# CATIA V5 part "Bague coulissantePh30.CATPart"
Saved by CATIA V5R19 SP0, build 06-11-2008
Part number: Bague coulissante
Bounding box of the stored display mesh (mm): x -20 to 20, y -20 to 20, z 1.42 to 25
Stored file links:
  C:\Users\Laurent\Desktop\Sujet National E33\CFAO Catia\Bague coulissantePh30.CATPart
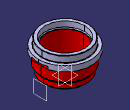
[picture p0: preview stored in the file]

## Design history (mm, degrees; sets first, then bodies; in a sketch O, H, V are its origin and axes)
Body1 (main body)
  Sketch1 on xy-plane, origin (0, 0, 0), H (1, 0, 0), V (0, 1, 0)
    circle A1 centre (0, 0) radius 22.5
    radius A1 = 22.5
  Pad1: profile Sketch1, direction (0, 0, 1), length 25
  Sketch2 on end face of Pad1, origin (0, 0, 25), H (1, 0, 0), V (0, 1, 0)
    circle A1 centre (0, 0) radius 17.45
    radius A1 = 17.45
  Pocket1: profile Sketch2, direction (0, 0, -1), length 4.78, outer side
  Sketch3 on end face of Pad1, origin (0, 0, 25), H (1, 0, 0), V (0, 1, 0)
    circle A1 centre (0, 0) radius 20
    radius A1 = 20
  Pocket2: profile Sketch3, direction (0, 0, -1), length 10, outer side
  Sketch4 on end face of Pad1, origin (0, 0, 25), H (1, 0, 0), V (0, 1, 0)
    circle A1 centre (0, 0) radius 10
    radius A1 = 10
  Pocket3: profile Sketch4, direction (0, 0, -1), through (limit type 3)
  Sketch5 on end face of Pad1, origin (0, 0, 25), H (1, 0, 0), V (0, 1, 0)
    circle A1 centre (0, 0) radius 14.95
    radius A1 = 14.95
  Pocket4: profile Sketch5, direction (0, 0, -1), length 4.78
  Sketch6 on zx-plane, origin (0, 0, 0), H (-1, 0, 0), V (0, 0, 1)
    axis line L1 (-25.6583, 20.6) -> (32.7674, 20.6)
    arc A1 centre (14.79, 20.6) radius 0.5 from (14.79, 20.1) to (14.79, 21.1) ccw
    point P3 (14.79, 20.6)
    reference projected line E1 (-17.45, 25) -> (17.45, 25) from edge [face of Pocket1 from Sketch2.A1 | end face of Pad1]
    line L2 (14.79, 20.1) -> (0, 20.1)
    point P4 (0, 20.1)
    line L3 (14.79, 21.1) -> (0, 21.1)
    point P5 (0, 21.1)
    line L4 (0, 20.1) -> (0, 21.1)
    reference projected line E2 through (0, 0) direction (0, 1) from axis of face of Pocket1 from Sketch2.A1
    distance L1 E1 = 4.4
    radius A1 = 0.5
    distance A1 E2 = 15.29
    horizontal: L1 H, L2 H, L3 H
    coincidence: P3 L1, P4 V, P5 V
    tangency: L3 A1, L2 A1
    vertical: L4 V
  Groove1: profile Sketch6, axis axis of face of Pocket2 from Sketch3.A1, angle 360
  Fillet1: radius 0.3, on edge [face of Pocket1 from Sketch2.A1 | end face of Pad1]; edge [end face of Pocket1 | face of Pocket1 from Sketch2.A1]
  Sketch7 on start face of Pad1, origin (0, 0, 0), H (1, 0, 0), V (0, -1, 0)
    circle A1 centre (0, 0) radius 23.7695
  Pocket5: profile Sketch7, direction (0, 0, 1), length 1.42
  Sketch8 on end face of Pocket5, origin (0, 0, 1.42), H (1, 0, 0), V (0, -1, 0)
    circle A1 centre (0, 0) radius 17.9915
    radius A1 = 17.9915
  Pocket6: profile Sketch8, direction (0, 0, 1), length 14.8, outer side
  Sketch9 on end face of Pocket5, origin (0, 0, 1.42), H (1, 0, 0), V (0, -1, 0)
    circle A1 centre (0, 0) radius 16.5
    radius A1 = 16.5
  Pocket7: profile Sketch9, direction (0, 0, 1), length 6.8, outer side
  Chamfer1: length 1.5, angle 45, on edge [face of Pocket7 from Sketch9.A1 | end face of Pocket5]
  Sketch10 on zx-plane, origin (0, 0, 0), H (-1, 0, 0), V (0, 0, 1)
    line L1 (15.5, 8.22) -> (15.5, 6.22)
    line L2 (15.5, 6.22) -> (31.9529, 6.22)
    line L3 (15.5, 8.22) -> (31.9529, 8.22)
    line L4 (31.9529, 8.22) -> (31.9529, 6.22)
    reference projected line E1 (14.5, 1.42) -> (-14.5, 1.42) from edge [face of Chamfer1 | end face of Pocket5]
    reference projected line E2 through (0, 0) direction (0, -1) from axis of face of Pocket7 from Sketch9.A1
    distance L3 E1 = 6.8
    distance L1 E2 = 15.5
    distance L3 L2 = 2
    vertical: L1 V, L4 V
    horizontal: L2 H, L3 H
  Groove2: profile Sketch10, axis axis of face of Chamfer1, angle 360
  Fillet2: radius 0.5, on edge [face of Groove2 from Sketch10.L1 | face of Groove2]; edge [face of Groove2 from Sketch10.L2 | face of Groove2 from Sketch10.L1]
  Sketch11 on end face of Pocket5, origin (0, 0, 1.42), H (1, 0, 0), V (0, -1, 0)
    circle A1 centre (0, 0) radius 14.2912
    radius A1 = 14.2912
  Pocket8: profile Sketch11, direction (0, 0, -1), through (limit type 3)
  Chamfer2: length 0.9, angle 30, on edge [end face of Pocket5 | face of Pocket8 from Sketch11.A1]
  Plane1: type Offset, Offset 19, RefPlane yz-plane
  Sketch12 on Plane1, origin (19, 0, 0), H (0, 1, 0), V (0, 0, 1)
    line L1 (-10, 18.22) -> (10, 18.22)
    line L2 (10, 18.22) -> (10, 14.8867)
    line L3 (10, 14.8867) -> (-10, 14.8867)
    line L4 (-10, 14.8867) -> (-10, 18.22)
    reference projected line E1 (20, 16.22) -> (-20, 16.22) from edge [face of Pocket2 from Sketch3.A1 | end face of Pocket6]
    reference projected line E2 through (0, 0) direction (0, -1) from axis of face of Pocket6 from Sketch8.A1
    reference projected line E3 through (0, 0) direction (0, -1) from axis of face of Pocket6 from Sketch8.A1
    distance L1 E1 = 2
    distance L2 E2 = 10
    distance L4 E3 = 10
    horizontal: L1 H, L3 H
    vertical: L2 V, L4 V
  Pocket9: profile Sketch12, direction (1, 0, 0), through (limit type 3)
  Mirror1: of Pocket9, about yz-plane
  Thread1: diameter 33, depth 4.8, pitch 1.5, on face of Pocket7 from Sketch9.A1, from end face of Pocket5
